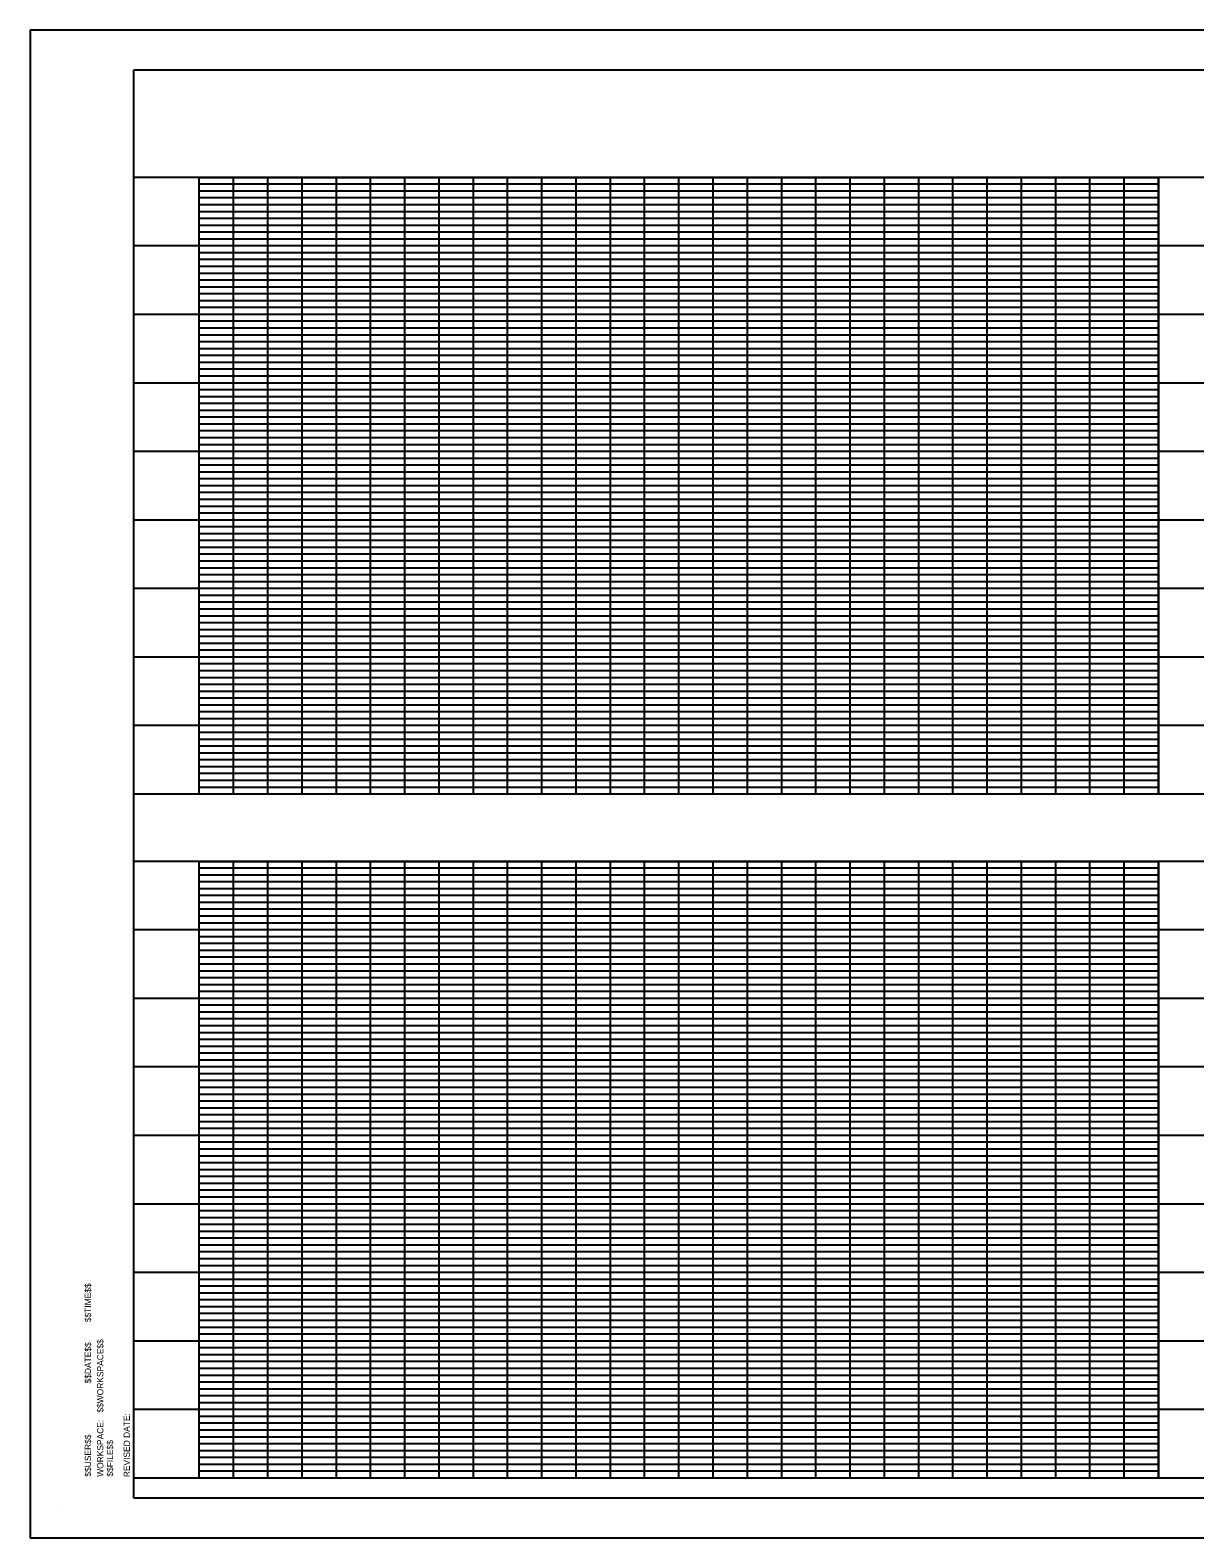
# Model space of a CAD drawing. Extents: x 1449378 to 1451078, y 2058337 to 2059437.
# Drawn here: x 1449378 to 1450228, y 2058337 to 2059437 of the extents above; entities that cross this region are included whole.
import ezdxf

# ---------------------------------------------------------------- set-up
doc = ezdxf.new("R2010")
doc.units = 0
for name, color, linetype in [('1', 7, 'Continuous'), ('G-ANNO-TEXT', 7, 'Continuous'), ('G-Border-Sheet', 7, 'Continuous'), ('G-Grid-Border-1', 7, 'Continuous'), ('G-Grid-Border-2', 7, 'Continuous'), ('G-Grid-Major-1', 7, 'Continuous'), ('G-Grid-Minor-1', 7, 'Continuous')]:
    doc.layers.add(name, color=color, linetype=linetype)

msp = doc.modelspace()

# ---------------------------------------------------------------- linework, layer by layer
at = {"layer": '1'}
msp.add_lwpolyline([(1451078.1, 2059436.5), (1449378.1, 2059436.5), (1449378.1, 2058336.5), (1451078.1, 2058336.5)], close=True, dxfattribs=at)
at = {"layer": 'G-ANNO-TEXT'}
msp.add_line((1449401.5, 2058357.9), (1449401.5, 2058357.9), dxfattribs=at)
at = {"layer": 'G-Border-Sheet'}
for p, q in [((1449453.9, 2059407.7), (1451049.3, 2059407.7)), ((1449453.9, 2058365.4), (1449453.9, 2059407.7)), ((1451049.3, 2058365.4), (1449453.9, 2058365.4))]:
    msp.add_line(p, q, dxfattribs=at)
at = {"layer": 'G-Grid-Border-1'}
for p, q in [((1450898.5, 2059329.1), (1449453.9, 2059329.1)), ((1451049.3, 2058879.1), (1449453.9, 2058879.1)), ((1451049.3, 2058830.1), (1449453.9, 2058830.1)), ((1451049.3, 2058380.1), (1449453.9, 2058380.1))]:
    msp.add_line(p, q, dxfattribs=at)
for points in [[(1449501.6, 2059329.1), (1450201.6, 2059329.1), (1450201.6, 2058879.1), (1449501.6, 2058879.1)], [(1449501.6, 2058830.1), (1450201.6, 2058830.1), (1450201.6, 2058380.1), (1449501.6, 2058380.1)]]:
    msp.add_lwpolyline(points, close=True, dxfattribs=at)
at = {"layer": 'G-Grid-Border-2'}
for p, q in [((1450501.6, 2059329.1), (1449453.9, 2059329.1)), ((1451049.3, 2058879.1), (1449453.9, 2058879.1)), ((1451049.3, 2058830.1), (1449453.9, 2058830.1)), ((1449501.6, 2058380.1), (1449501.6, 2058830.1)), ((1451049.3, 2058380.1), (1449453.9, 2058380.1))]:
    msp.add_line(p, q, dxfattribs=at)
for points in [[(1449501.6, 2059329.1), (1450201.6, 2059329.1), (1450201.6, 2058879.1), (1449501.6, 2058879.1)], [(1449501.6, 2058830.1), (1450201.6, 2058830.1), (1450201.6, 2058380.1), (1449501.6, 2058380.1)]]:
    msp.add_lwpolyline(points, close=True, dxfattribs=at)
msp.add_lwpolyline([(1451001.6, 2058830.1), (1451001.6, 2058380.1), (1449501.6, 2058380.1), (1449501.6, 2058830.1)], dxfattribs=at)
at = {"layer": 'G-Grid-Major-1'}
for p, q in [((1449501.6, 2058879.1), (1449501.6, 2059329.1)), ((1449551.6, 2058879.1), (1449551.6, 2059329.1)), ((1449601.6, 2058879.1), (1449601.6, 2059329.1)), ((1449651.6, 2058879.1), (1449651.6, 2059329.1)), ((1449701.6, 2058879.1), (1449701.6, 2059329.1)), ((1449751.6, 2058879.1), (1449751.6, 2059329.1)), ((1449801.6, 2058879.1), (1449801.6, 2059329.1)), ((1449851.6, 2058879.1), (1449851.6, 2059329.1)), ((1449901.6, 2058879.1), (1449901.6, 2059329.1)), ((1449951.6, 2058879.1), (1449951.6, 2059329.1)), ((1450001.6, 2058879.1), (1450001.6, 2059329.1)), ((1450051.6, 2058879.1), (1450051.6, 2059329.1)), ((1450101.6, 2058879.1), (1450101.6, 2059329.1)), ((1450151.6, 2058879.1), (1450151.6, 2059329.1)), ((1450201.6, 2058879.1), (1450201.6, 2059329.1)), ((1450201.6, 2059279.1), (1449453.9, 2059279.1)), ((1450901.6, 2059279.1), (1450201.6, 2059279.1)), ((1450201.6, 2059229.1), (1449453.9, 2059229.1)), ((1450901.6, 2059229.1), (1450201.6, 2059229.1)), ((1450201.6, 2059179.1), (1449453.9, 2059179.1)), ((1451049.3, 2059179.1), (1450201.6, 2059179.1)), ((1450201.6, 2059129.1), (1449453.9, 2059129.1)), ((1451049.3, 2059129.1), (1450201.6, 2059129.1)), ((1450201.6, 2059079.1), (1449453.9, 2059079.1)), ((1451049.3, 2059079.1), (1450201.6, 2059079.1)), ((1450201.6, 2059029.1), (1449453.9, 2059029.1)), ((1451049.3, 2059029.1), (1450201.6, 2059029.1)), ((1450201.6, 2058979.1), (1449453.9, 2058979.1)), ((1451049.3, 2058979.1), (1450201.6, 2058979.1)), ((1450201.6, 2058929.1), (1449453.9, 2058929.1)), ((1451049.3, 2058929.1), (1450201.6, 2058929.1)), ((1449551.6, 2058380.1), (1449551.6, 2058830.1)), ((1449601.6, 2058380.1), (1449601.6, 2058830.1)), ((1449651.6, 2058380.1), (1449651.6, 2058830.1)), ((1449701.6, 2058380.1), (1449701.6, 2058830.1)), ((1449751.6, 2058380.1), (1449751.6, 2058830.1)), ((1449801.6, 2058380.1), (1449801.6, 2058830.1)), ((1449851.6, 2058380.1), (1449851.6, 2058830.1)), ((1449901.6, 2058380.1), (1449901.6, 2058830.1)), ((1449951.6, 2058380.1), (1449951.6, 2058830.1)), ((1450001.6, 2058380.1), (1450001.6, 2058830.1)), ((1450051.6, 2058380.1), (1450051.6, 2058830.1)), ((1450101.6, 2058380.1), (1450101.6, 2058830.1)), ((1450151.6, 2058380.1), (1450151.6, 2058830.1)), ((1450201.6, 2058380.1), (1450201.6, 2058830.1)), ((1450201.6, 2058780.1), (1449453.9, 2058780.1)), ((1451049.3, 2058780.1), (1450201.6, 2058780.1)), ((1450201.6, 2058730.1), (1449453.9, 2058730.1)), ((1451049.3, 2058730.1), (1450201.6, 2058730.1)), ((1450201.6, 2058680.1), (1449453.9, 2058680.1)), ((1451049.3, 2058680.1), (1450201.6, 2058680.1)), ((1450201.6, 2058630.1), (1449453.9, 2058630.1)), ((1451049.3, 2058630.1), (1450201.6, 2058630.1)), ((1450201.6, 2058580.1), (1449453.9, 2058580.1)), ((1451049.3, 2058580.1), (1450201.6, 2058580.1)), ((1450201.6, 2058530.1), (1449453.9, 2058530.1)), ((1451049.3, 2058530.1), (1450201.6, 2058530.1)), ((1450201.6, 2058480.1), (1449453.9, 2058480.1)), ((1451049.3, 2058480.1), (1450201.6, 2058480.1)), ((1450201.6, 2058430.1), (1449453.9, 2058430.1)), ((1451049.3, 2058430.1), (1450201.6, 2058430.1))]:
    msp.add_line(p, q, dxfattribs=at)
at = {"layer": 'G-Grid-Minor-1'}
for p, q in [((1450201.6, 2059324.1), (1449501.6, 2059324.1)), ((1449526.6, 2058879.1), (1449526.6, 2059329.1)), ((1449576.6, 2058879.1), (1449576.6, 2059329.1)), ((1449626.6, 2058879.1), (1449626.6, 2059329.1)), ((1449676.6, 2058879.1), (1449676.6, 2059329.1)), ((1449726.6, 2058879.1), (1449726.6, 2059329.1)), ((1449776.6, 2058879.1), (1449776.6, 2059329.1)), ((1449826.6, 2058879.1), (1449826.6, 2059329.1)), ((1449876.6, 2058879.1), (1449876.6, 2059329.1)), ((1449926.6, 2058879.1), (1449926.6, 2059329.1)), ((1449976.6, 2058879.1), (1449976.6, 2059329.1)), ((1450026.6, 2058879.1), (1450026.6, 2059329.1)), ((1450076.6, 2058879.1), (1450076.6, 2059329.1)), ((1450126.6, 2058879.1), (1450126.6, 2059329.1)), ((1450176.6, 2058879.1), (1450176.6, 2059329.1)), ((1450201.6, 2059319.1), (1449501.6, 2059319.1)), ((1450201.6, 2059314.1), (1449501.6, 2059314.1)), ((1450201.6, 2059309.1), (1449501.6, 2059309.1)), ((1450201.6, 2059304.1), (1449501.6, 2059304.1)), ((1450201.6, 2059299.1), (1449501.6, 2059299.1)), ((1450201.6, 2059294.1), (1449501.6, 2059294.1)), ((1450201.6, 2059289.1), (1449501.6, 2059289.1)), ((1450201.6, 2059284.1), (1449501.6, 2059284.1)), ((1450201.6, 2059274.1), (1449501.6, 2059274.1)), ((1450201.6, 2059269.1), (1449501.6, 2059269.1)), ((1450201.6, 2059264.1), (1449501.6, 2059264.1)), ((1450201.6, 2059259.1), (1449501.6, 2059259.1)), ((1450201.6, 2059254.1), (1449501.6, 2059254.1)), ((1450201.6, 2059249.1), (1449501.6, 2059249.1)), ((1450201.6, 2059244.1), (1449501.6, 2059244.1)), ((1450201.6, 2059239.1), (1449501.6, 2059239.1)), ((1450201.6, 2059234.1), (1449501.6, 2059234.1)), ((1450201.6, 2059224.1), (1449501.6, 2059224.1)), ((1450201.6, 2059219.1), (1449501.6, 2059219.1)), ((1450201.6, 2059214.1), (1449501.6, 2059214.1)), ((1450201.6, 2059209.1), (1449501.6, 2059209.1)), ((1450201.6, 2059204.1), (1449501.6, 2059204.1)), ((1450201.6, 2059199.1), (1449501.6, 2059199.1)), ((1450201.6, 2059194.1), (1449501.6, 2059194.1)), ((1450201.6, 2059189.1), (1449501.6, 2059189.1)), ((1450201.6, 2059184.1), (1449501.6, 2059184.1)), ((1450201.6, 2059174.1), (1449501.6, 2059174.1)), ((1450201.6, 2059169.1), (1449501.6, 2059169.1)), ((1450201.6, 2059164.1), (1449501.6, 2059164.1)), ((1450201.6, 2059159.1), (1449501.6, 2059159.1)), ((1450201.6, 2059154.1), (1449501.6, 2059154.1)), ((1450201.6, 2059149.1), (1449501.6, 2059149.1)), ((1450201.6, 2059144.1), (1449501.6, 2059144.1)), ((1450201.6, 2059139.1), (1449501.6, 2059139.1)), ((1450201.6, 2059134.1), (1449501.6, 2059134.1)), ((1450201.6, 2059124.1), (1449501.6, 2059124.1)), ((1450201.6, 2059119.1), (1449501.6, 2059119.1)), ((1450201.6, 2059114.1), (1449501.6, 2059114.1)), ((1450201.6, 2059109.1), (1449501.6, 2059109.1)), ((1450201.6, 2059104.1), (1449501.6, 2059104.1)), ((1450201.6, 2059099.1), (1449501.6, 2059099.1)), ((1450201.6, 2059094.1), (1449501.6, 2059094.1)), ((1450201.6, 2059089.1), (1449501.6, 2059089.1)), ((1450201.6, 2059084.1), (1449501.6, 2059084.1)), ((1450201.6, 2059074.1), (1449501.6, 2059074.1)), ((1450201.6, 2059069.1), (1449501.6, 2059069.1)), ((1450201.6, 2059064.1), (1449501.6, 2059064.1)), ((1450201.6, 2059059.1), (1449501.6, 2059059.1)), ((1450201.6, 2059054.1), (1449501.6, 2059054.1)), ((1450201.6, 2059049.1), (1449501.6, 2059049.1)), ((1450201.6, 2059044.1), (1449501.6, 2059044.1)), ((1450201.6, 2059039.1), (1449501.6, 2059039.1)), ((1450201.6, 2059034.1), (1449501.6, 2059034.1)), ((1450201.6, 2059024.1), (1449501.6, 2059024.1)), ((1450201.6, 2059019.1), (1449501.6, 2059019.1)), ((1450201.6, 2059014.1), (1449501.6, 2059014.1)), ((1450201.6, 2059009.1), (1449501.6, 2059009.1)), ((1450201.6, 2059004.1), (1449501.6, 2059004.1)), ((1450201.6, 2058999.1), (1449501.6, 2058999.1)), ((1450201.6, 2058994.1), (1449501.6, 2058994.1)), ((1450201.6, 2058989.1), (1449501.6, 2058989.1)), ((1450201.6, 2058984.1), (1449501.6, 2058984.1)), ((1450201.6, 2058974.1), (1449501.6, 2058974.1)), ((1450201.6, 2058969.1), (1449501.6, 2058969.1)), ((1450201.6, 2058964.1), (1449501.6, 2058964.1)), ((1450201.6, 2058959.1), (1449501.6, 2058959.1)), ((1450201.6, 2058954.1), (1449501.6, 2058954.1)), ((1450201.6, 2058949.1), (1449501.6, 2058949.1)), ((1450201.6, 2058944.1), (1449501.6, 2058944.1)), ((1450201.6, 2058939.1), (1449501.6, 2058939.1)), ((1450201.6, 2058934.1), (1449501.6, 2058934.1)), ((1450201.6, 2058924.1), (1449501.6, 2058924.1)), ((1450201.6, 2058919.1), (1449501.6, 2058919.1)), ((1450201.6, 2058914.1), (1449501.6, 2058914.1)), ((1450201.6, 2058909.1), (1449501.6, 2058909.1)), ((1450201.6, 2058904.1), (1449501.6, 2058904.1)), ((1450201.6, 2058899.1), (1449501.6, 2058899.1)), ((1450201.6, 2058894.1), (1449501.6, 2058894.1)), ((1450201.6, 2058889.1), (1449501.6, 2058889.1)), ((1450201.6, 2058884.1), (1449501.6, 2058884.1)), ((1449526.6, 2058380.1), (1449526.6, 2058830.1)), ((1449576.6, 2058380.1), (1449576.6, 2058830.1)), ((1449626.6, 2058380.1), (1449626.6, 2058830.1)), ((1449676.6, 2058380.1), (1449676.6, 2058830.1)), ((1449726.6, 2058380.1), (1449726.6, 2058830.1)), ((1449776.6, 2058380.1), (1449776.6, 2058830.1)), ((1449826.6, 2058380.1), (1449826.6, 2058830.1)), ((1449876.6, 2058380.1), (1449876.6, 2058830.1)), ((1449926.6, 2058380.1), (1449926.6, 2058830.1)), ((1449976.6, 2058380.1), (1449976.6, 2058830.1)), ((1450026.6, 2058380.1), (1450026.6, 2058830.1)), ((1450076.6, 2058380.1), (1450076.6, 2058830.1)), ((1450126.6, 2058380.1), (1450126.6, 2058830.1)), ((1450176.6, 2058380.1), (1450176.6, 2058830.1)), ((1450201.6, 2058825.1), (1449501.6, 2058825.1)), ((1450201.6, 2058820.1), (1449501.6, 2058820.1)), ((1450201.6, 2058815.1), (1449501.6, 2058815.1)), ((1450201.6, 2058810.1), (1449501.6, 2058810.1)), ((1450201.6, 2058805.1), (1449501.6, 2058805.1)), ((1450201.6, 2058800.1), (1449501.6, 2058800.1)), ((1450201.6, 2058795.1), (1449501.6, 2058795.1)), ((1450201.6, 2058790.1), (1449501.6, 2058790.1)), ((1450201.6, 2058785.1), (1449501.6, 2058785.1)), ((1450201.6, 2058775.1), (1449501.6, 2058775.1)), ((1450201.6, 2058770.1), (1449501.6, 2058770.1)), ((1450201.6, 2058765.1), (1449501.6, 2058765.1)), ((1450201.6, 2058760.1), (1449501.6, 2058760.1)), ((1450201.6, 2058755.1), (1449501.6, 2058755.1)), ((1450201.6, 2058750.1), (1449501.6, 2058750.1)), ((1450201.6, 2058745.1), (1449501.6, 2058745.1)), ((1450201.6, 2058740.1), (1449501.6, 2058740.1)), ((1450201.6, 2058735.1), (1449501.6, 2058735.1)), ((1450201.6, 2058725.1), (1449501.6, 2058725.1)), ((1450201.6, 2058720.1), (1449501.6, 2058720.1)), ((1450201.6, 2058715.1), (1449501.6, 2058715.1)), ((1450201.6, 2058710.1), (1449501.6, 2058710.1)), ((1450201.6, 2058705.1), (1449501.6, 2058705.1)), ((1450201.6, 2058700.1), (1449501.6, 2058700.1)), ((1450201.6, 2058695.1), (1449501.6, 2058695.1)), ((1450201.6, 2058690.1), (1449501.6, 2058690.1)), ((1450201.6, 2058685.1), (1449501.6, 2058685.1)), ((1450201.6, 2058675.1), (1449501.6, 2058675.1)), ((1450201.6, 2058670.1), (1449501.6, 2058670.1)), ((1450201.6, 2058665.1), (1449501.6, 2058665.1)), ((1450201.6, 2058660.1), (1449501.6, 2058660.1)), ((1450201.6, 2058655.1), (1449501.6, 2058655.1)), ((1450201.6, 2058650.1), (1449501.6, 2058650.1)), ((1450201.6, 2058645.1), (1449501.6, 2058645.1)), ((1450201.6, 2058640.1), (1449501.6, 2058640.1)), ((1450201.6, 2058635.1), (1449501.6, 2058635.1)), ((1450201.6, 2058625.1), (1449501.6, 2058625.1)), ((1450201.6, 2058620.1), (1449501.6, 2058620.1)), ((1450201.6, 2058615.1), (1449501.6, 2058615.1)), ((1450201.6, 2058610.1), (1449501.6, 2058610.1)), ((1450201.6, 2058605.1), (1449501.6, 2058605.1)), ((1450201.6, 2058600.1), (1449501.6, 2058600.1)), ((1450201.6, 2058595.1), (1449501.6, 2058595.1)), ((1450201.6, 2058590.1), (1449501.6, 2058590.1)), ((1450201.6, 2058585.1), (1449501.6, 2058585.1)), ((1450201.6, 2058575.1), (1449501.6, 2058575.1)), ((1450201.6, 2058570.1), (1449501.6, 2058570.1)), ((1450201.6, 2058565.1), (1449501.6, 2058565.1)), ((1450201.6, 2058560.1), (1449501.6, 2058560.1)), ((1450201.6, 2058555.1), (1449501.6, 2058555.1)), ((1450201.6, 2058550.1), (1449501.6, 2058550.1)), ((1450201.6, 2058545.1), (1449501.6, 2058545.1)), ((1450201.6, 2058540.1), (1449501.6, 2058540.1)), ((1450201.6, 2058535.1), (1449501.6, 2058535.1)), ((1450201.6, 2058525.1), (1449501.6, 2058525.1)), ((1450201.6, 2058520.1), (1449501.6, 2058520.1)), ((1450201.6, 2058515.1), (1449501.6, 2058515.1)), ((1450201.6, 2058510.1), (1449501.6, 2058510.1)), ((1450201.6, 2058505.1), (1449501.6, 2058505.1)), ((1450201.6, 2058500.1), (1449501.6, 2058500.1)), ((1450201.6, 2058495.1), (1449501.6, 2058495.1)), ((1450201.6, 2058490.1), (1449501.6, 2058490.1)), ((1450201.6, 2058485.1), (1449501.6, 2058485.1)), ((1450201.6, 2058475.1), (1449501.6, 2058475.1)), ((1450201.6, 2058470.1), (1449501.6, 2058470.1)), ((1450201.6, 2058465.1), (1449501.6, 2058465.1)), ((1450201.6, 2058460.1), (1449501.6, 2058460.1)), ((1450201.6, 2058455.1), (1449501.6, 2058455.1)), ((1450201.6, 2058450.1), (1449501.6, 2058450.1)), ((1450201.6, 2058445.1), (1449501.6, 2058445.1)), ((1450201.6, 2058440.1), (1449501.6, 2058440.1)), ((1450201.6, 2058435.1), (1449501.6, 2058435.1)), ((1450201.6, 2058425.1), (1449501.6, 2058425.1)), ((1450201.6, 2058420.1), (1449501.6, 2058420.1)), ((1450201.6, 2058415.1), (1449501.6, 2058415.1)), ((1450201.6, 2058410.1), (1449501.6, 2058410.1)), ((1450201.6, 2058405.1), (1449501.6, 2058405.1)), ((1450201.6, 2058400.1), (1449501.6, 2058400.1)), ((1450201.6, 2058395.1), (1449501.6, 2058395.1)), ((1450201.6, 2058390.1), (1449501.6, 2058390.1)), ((1450201.6, 2058385.1), (1449501.6, 2058385.1))]:
    msp.add_line(p, q, dxfattribs=at)
msp.add_lwpolyline([(1451001.6, 2059179.1), (1451001.6, 2058879.1), (1449501.6, 2058879.1), (1449501.6, 2059329.1)], dxfattribs=at)

# ---------------------------------------------------------------- texts
at = {"layer": 'G-ANNO-TEXT'}
for s, p in [('$$TIME$$', (1449422.6, 2058493.9)), ('$$DATE$$', (1449422.6, 2058449.2)), ('$$WORKSPACE$$', (1449431.6, 2058427.9)), ('WORKSPACE:', (1449431.6, 2058381.1)), ('REVISED DATE:', (1449450.9, 2058380.8)), ('$$USER$$', (1449422.6, 2058381.2)), ('$$FILE$$', (1449438.7, 2058381.2))]:
    msp.add_text(s, height=4.59, rotation=90, dxfattribs=at).set_placement(p)

doc.saveas('drawing.dxf')
